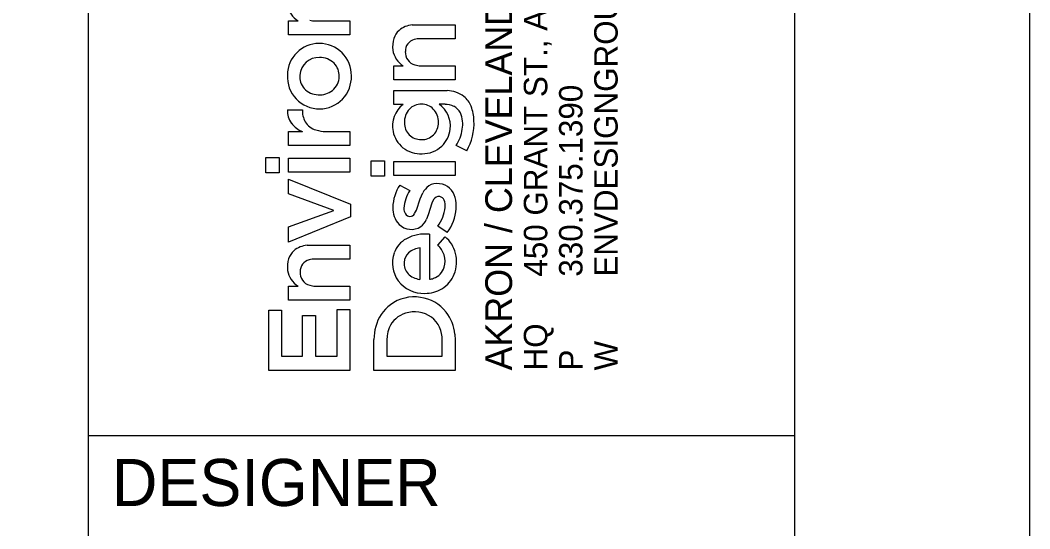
# Model space of a CAD drawing. Extents: x -0.3 to 34, y 0 to 22.
# Drawn here: x 31.855 to 34, y 2.302 to 3.382 of the extents above; entities that cross this region are included whole.
import ezdxf

# ---------------------------------------------------------------- set-up
doc = ezdxf.new("R2010")
doc.units = 0
for name, color, linetype in [('PM_X_CL_Pass_Proh_Lt', 7, 'Continuous'), ('PM_X_Edge_Line', 7, 'Continuous'), ('PM_X_Stop_Line', 7, 'Continuous')]:
    doc.layers.add(name, color=color, linetype=linetype)

msp = doc.modelspace()

# ---------------------------------------------------------------- linework, layer by layer
at = {"layer": 'PM_X_CL_Pass_Proh_Lt'}
msp.add_lwpolyline([(0, 0), (34, 0), (34, 22), (0, 22)], close=True, dxfattribs=at)
at = {"layer": 'PM_X_Edge_Line'}
for p, q in [((32.4254, 3.3509), (32.4254, 3.3807)), ((32.4254, 3.3807), (32.4455, 3.3807)), ((32.4822, 3.3807), (32.5557, 3.3807)), ((32.5557, 3.3807), (32.5557, 3.351)), ((32.6878, 3.3722), (32.6963, 3.3727)), ((32.6963, 3.3727), (32.7792, 3.3727)), ((32.7792, 3.3727), (32.7792, 3.3429)), ((32.5557, 3.351), (32.4254, 3.3509)), ((32.7792, 3.3429), (32.7048, 3.3428)), ((32.6489, 3.2557), (32.6489, 3.2855)), ((32.6489, 3.2855), (32.669, 3.2855)), ((32.7057, 3.2855), (32.7791, 3.2855)), ((32.7791, 3.2855), (32.7792, 3.2558)), ((32.7792, 3.2558), (32.6489, 3.2557)), ((32.6489, 3.2034), (32.6489, 3.2332)), ((32.6489, 3.2332), (32.7524, 3.2332)), ((32.7524, 3.2332), (32.7619, 3.2329)), ((32.6684, 3.2034), (32.6489, 3.2034)), ((32.7576, 3.2036), (32.7449, 3.2036)), ((32.423, 3.1919), (32.4545, 3.1919)), ((32.4254, 3.1159), (32.4254, 3.1458)), ((32.4254, 3.1458), (32.4547, 3.1458)), ((32.5041, 3.1458), (32.5557, 3.1457)), ((32.5557, 3.1457), (32.5556, 3.1159)), ((32.5556, 3.1159), (32.4254, 3.1159)), ((32.8036, 3.1049), (32.7812, 3.116)), ((32.3771, 3.0582), (32.3771, 3.0903)), ((32.3771, 3.0903), (32.4054, 3.0903)), ((32.4054, 3.0903), (32.4054, 3.0582)), ((32.4254, 3.0594), (32.4254, 3.0893)), ((32.4254, 3.0893), (32.5557, 3.0893)), ((32.5557, 3.0893), (32.5557, 3.0594)), ((32.6005, 3.0511), (32.6005, 3.0832)), ((32.6005, 3.0832), (32.6289, 3.0832)), ((32.6289, 3.0832), (32.6289, 3.0511)), ((32.6489, 3.0523), (32.6489, 3.0822)), ((32.6489, 3.0822), (32.7792, 3.0822)), ((32.7792, 3.0822), (32.7792, 3.0523)), ((32.4054, 3.0582), (32.3771, 3.0582)), ((32.5557, 3.0594), (32.4254, 3.0594)), ((32.6289, 3.0511), (32.6005, 3.0511)), ((32.7792, 3.0523), (32.6489, 3.0523)), ((32.4254, 3.0133), (32.4254, 3.0446)), ((32.4254, 3.0446), (32.5567, 2.9913)), ((32.6615, 3.0321), (32.6827, 3.0203)), ((32.5212, 2.978), (32.4254, 3.0133)), ((32.7048, 3.0026), (32.7104, 3.0153)), ((32.5567, 2.9913), (32.5567, 2.9644)), ((32.6967, 2.9787), (32.7048, 3.0026)), ((32.7298, 2.9933), (32.7221, 2.9688)), ((32.7334, 3.001), (32.7298, 2.9933)), ((32.4254, 2.9429), (32.5212, 2.978)), ((32.5567, 2.9644), (32.4254, 2.9109)), ((32.693, 2.9712), (32.6967, 2.9787)), ((32.7221, 2.9688), (32.7182, 2.9592)), ((32.4254, 2.9109), (32.4254, 2.9429)), ((32.7621, 2.9314), (32.742, 2.9447)), ((32.7245, 2.9275), (32.7246, 2.8319)), ((32.7423, 2.9046), (32.7577, 2.922)), ((32.4644, 2.904), (32.4729, 2.9044)), ((32.4729, 2.9044), (32.5557, 2.9044)), ((32.5557, 2.9044), (32.5557, 2.8746)), ((32.7049, 2.8318), (32.7049, 2.8983)), ((32.5557, 2.8746), (32.4814, 2.8746)), ((32.7036, 2.8317), (32.7049, 2.8318)), ((32.4254, 2.7875), (32.4254, 2.8173)), ((32.4254, 2.8173), (32.4455, 2.8173)), ((32.4822, 2.8173), (32.5557, 2.8173)), ((32.5557, 2.8173), (32.5557, 2.7876)), ((32.5557, 2.7876), (32.4254, 2.7875)), ((32.5286, 2.6683), (32.5286, 2.7672)), ((32.5286, 2.7672), (32.5557, 2.7672)), ((32.5557, 2.7672), (32.5557, 2.6379)), ((32.383, 2.6379), (32.383, 2.766)), ((32.383, 2.766), (32.4101, 2.766)), ((32.4101, 2.766), (32.4101, 2.6683)), ((32.455, 2.6683), (32.455, 2.7549)), ((32.455, 2.7549), (32.4822, 2.7549)), ((32.4822, 2.7549), (32.4822, 2.6683)), ((32.6064, 2.638), (32.6064, 2.704)), ((32.6347, 2.7118), (32.6341, 2.7023)), ((32.7785, 2.715), (32.7792, 2.7021)), ((32.6341, 2.7023), (32.6341, 2.6684)), ((32.7515, 2.6683), (32.7515, 2.7024)), ((32.7792, 2.7021), (32.7792, 2.638)), ((32.4101, 2.6683), (32.455, 2.6683)), ((32.4822, 2.6683), (32.5286, 2.6683)), ((32.6341, 2.6684), (32.7515, 2.6683)), ((32.5557, 2.6379), (32.383, 2.6379)), ((32.7792, 2.638), (32.6064, 2.638))]:
    msp.add_line(p, q, dxfattribs=at)
for points in [[(32.4254, 3.3509), (32.4254, 3.3807), (32.4455, 3.3807)], [(32.4822, 3.3807), (32.5557, 3.3807), (32.5557, 3.351), (32.4254, 3.3509)], [(32.6878, 3.3722), (32.6963, 3.3727), (32.7792, 3.3727), (32.7792, 3.3429), (32.7048, 3.3428)], [(32.6489, 3.2557), (32.6489, 3.2855), (32.669, 3.2855)], [(32.7057, 3.2855), (32.7791, 3.2855), (32.7792, 3.2558), (32.6489, 3.2557)], [(32.6684, 3.2034), (32.6489, 3.2034), (32.6489, 3.2332), (32.7524, 3.2332), (32.7619, 3.2329)], [(32.7576, 3.2036), (32.7449, 3.2036)], [(32.423, 3.1919), (32.4545, 3.1919)], [(32.4254, 3.1159), (32.4254, 3.1458), (32.4547, 3.1458)], [(32.5041, 3.1458), (32.5557, 3.1457), (32.5556, 3.1159), (32.4254, 3.1159)], [(32.8036, 3.1049), (32.7812, 3.116)], [(32.6615, 3.0321), (32.6827, 3.0203)], [(32.693, 2.9712), (32.6967, 2.9787), (32.7048, 3.0026), (32.7104, 3.0153)], [(32.7334, 3.001), (32.7298, 2.9933), (32.7221, 2.9688), (32.7182, 2.9592)], [(32.7621, 2.9314), (32.742, 2.9447)], [(32.7245, 2.9275), (32.7246, 2.8319)], [(32.7423, 2.9046), (32.7577, 2.922)], [(32.4644, 2.904), (32.4729, 2.9044), (32.5557, 2.9044), (32.5557, 2.8746), (32.4814, 2.8746)], [(32.7036, 2.8317), (32.7049, 2.8318), (32.7049, 2.8983)], [(32.4254, 2.7875), (32.4254, 2.8173), (32.4455, 2.8173)], [(32.4822, 2.8173), (32.5557, 2.8173), (32.5557, 2.7876), (32.4254, 2.7875)], [(32.7785, 2.715), (32.7792, 2.7021), (32.7792, 2.638), (32.6064, 2.638)], [(32.6064, 2.638), (32.6064, 2.704)], [(32.6347, 2.7118), (32.6341, 2.7023), (32.6341, 2.6684), (32.7515, 2.6683), (32.7515, 2.7024)]]:
    msp.add_lwpolyline(points, dxfattribs=at)
for points in [[(32.3771, 3.0582), (32.3771, 3.0903), (32.4054, 3.0903), (32.4054, 3.0582)], [(32.4254, 3.0594), (32.4254, 3.0893), (32.5557, 3.0893), (32.5557, 3.0594)], [(32.6005, 3.0511), (32.6005, 3.0832), (32.6289, 3.0832), (32.6289, 3.0511)], [(32.6489, 3.0523), (32.6489, 3.0822), (32.7792, 3.0822), (32.7792, 3.0523)], [(32.4254, 2.9109), (32.4254, 2.9429), (32.5212, 2.978), (32.4254, 3.0133), (32.4254, 3.0446), (32.5567, 2.9913), (32.5567, 2.9644)], [(32.383, 2.6379), (32.383, 2.766), (32.4101, 2.766), (32.4101, 2.6683), (32.455, 2.6683), (32.455, 2.7549), (32.4822, 2.7549), (32.4822, 2.6683), (32.5286, 2.6683), (32.5286, 2.7672), (32.5557, 2.7672), (32.5557, 2.6379)]]:
    msp.add_lwpolyline(points, close=True, dxfattribs=at)
for centre, radius, start, end in [((32.4703, 3.4214), 0.0476, 188.9646, 238.6987), ((32.4703, 3.4214), 0.0476, 188.9646, 238.6987), ((32.4818, 3.4229), 0.0421, 254.0891, 270.5284), ((32.4818, 3.4229), 0.0421, 254.0891, 270.5284), ((32.6922, 3.3225), 0.0499, 94.9706, 130.2248), ((32.6922, 3.3225), 0.0499, 94.9706, 130.2248), ((32.6869, 3.3309), 0.0402, 132.2238, 161.6823), ((32.6869, 3.3309), 0.0402, 132.2238, 161.6823), ((32.4901, 3.2654), 0.0674, 89.8476, 179.6405), ((32.4901, 3.2654), 0.0674, 89.8476, 179.6405), ((32.4906, 3.2647), 0.0681, 359.5401, 90.2114), ((32.4906, 3.2647), 0.0681, 359.5401, 90.2114), ((32.7022, 3.3264), 0.056, 162.274, 187.7917), ((32.7022, 3.3264), 0.056, 162.274, 187.7917), ((32.6983, 3.3169), 0.025, 103.6868, 182.214), ((32.6983, 3.3169), 0.025, 103.6868, 182.214), ((32.7045, 3.2968), 0.046, 89.6051, 105.3303), ((32.7045, 3.2968), 0.046, 89.6051, 105.3303), ((32.6937, 3.3262), 0.0476, 188.9646, 238.6987), ((32.6937, 3.3262), 0.0476, 188.9646, 238.6987), ((32.7008, 3.3138), 0.0276, 175.5844, 255.1382), ((32.7008, 3.3138), 0.0276, 175.5844, 255.1382), ((32.4892, 3.2626), 0.0404, 87.0481, 175.5726), ((32.4892, 3.2626), 0.0404, 87.0481, 175.5726), ((32.492, 3.26), 0.043, 45.8426, 90.9801), ((32.492, 3.26), 0.043, 45.8426, 90.9801), ((32.4946, 3.2642), 0.0382, 357.8857, 44.159), ((32.4946, 3.2642), 0.0382, 357.8857, 44.159), ((32.7053, 3.3277), 0.0421, 254.0891, 270.5284), ((32.7053, 3.3277), 0.0421, 254.0891, 270.5284), ((32.4908, 3.2621), 0.0682, 176.8344, 270.4038), ((32.4908, 3.2621), 0.0682, 176.8344, 270.4038), ((32.4873, 3.2625), 0.0385, 175.1538, 221.1471), ((32.4873, 3.2625), 0.0385, 175.1538, 221.1471), ((32.4912, 3.2614), 0.0675, 270.0624, 2.3776), ((32.4912, 3.2614), 0.0675, 270.0624, 2.3776), ((32.4945, 3.2632), 0.0383, 308.2894, 359.4347), ((32.4945, 3.2632), 0.0383, 308.2894, 359.4347), ((32.4892, 3.2661), 0.0423, 223.0999, 268.8089), ((32.4892, 3.2661), 0.0423, 223.0999, 268.8089), ((32.491, 3.2679), 0.0442, 266.5651, 308.0608), ((32.491, 3.2679), 0.0442, 266.5651, 308.0608), ((32.7591, 3.1679), 0.065, 53.4034, 87.4906), ((32.7591, 3.1679), 0.065, 53.4034, 87.4906), ((32.7652, 3.1804), 0.0514, 21.6075, 50.5577), ((32.7652, 3.1804), 0.0514, 21.6075, 50.5577), ((32.7029, 3.1581), 0.0569, 127.3748, 192.2247), ((32.7029, 3.1581), 0.0569, 127.3748, 192.2247), ((32.7069, 3.1693), 0.0346, 88.473, 136.4256), ((32.7069, 3.1693), 0.0346, 88.473, 136.4256), ((32.7081, 3.1696), 0.0342, 44.2719, 90.4762), ((32.7081, 3.1696), 0.0342, 44.2719, 90.4762), ((32.7142, 3.1583), 0.0547, 352.1125, 55.923), ((32.7142, 3.1583), 0.0547, 352.1125, 55.923), ((32.7567, 3.1572), 0.0463, 65.0169, 88.8011), ((32.7567, 3.1572), 0.0463, 65.0169, 88.8011), ((32.7626, 3.1716), 0.0309, 26.2681, 63.803), ((32.7626, 3.1716), 0.0309, 26.2681, 63.803), ((32.7307, 3.1671), 0.0884, 1.1514, 21.3627), ((32.7307, 3.1671), 0.0884, 1.1514, 21.3627), ((32.4662, 3.1888), 0.0433, 175.8731, 216.3475), ((32.4662, 3.1888), 0.0433, 175.8731, 216.3475), ((32.5009, 3.1895), 0.0464, 176.9688, 209.6064), ((32.5009, 3.1895), 0.0464, 176.9688, 209.6064), ((32.7114, 3.166), 0.0401, 137.4674, 182.3324), ((32.7114, 3.166), 0.0401, 137.4674, 182.3324), ((32.7037, 3.166), 0.04, 358.5714, 43.5376), ((32.7037, 3.166), 0.04, 358.5714, 43.5376), ((32.7357, 3.1615), 0.0595, 349.3073, 23.4307), ((32.7357, 3.1615), 0.0595, 349.3073, 23.4307), ((32.4747, 3.1972), 0.0551, 218.0981, 248.7907), ((32.4747, 3.1972), 0.0551, 218.0981, 248.7907), ((32.4951, 3.1881), 0.0408, 211.9447, 253.2028), ((32.4951, 3.1881), 0.0408, 211.9447, 253.2028), ((32.7065, 3.1637), 0.0351, 178.8821, 271.0837), ((32.7065, 3.1637), 0.0351, 178.8821, 271.0837), ((32.7082, 3.164), 0.0355, 268.2788, 1.5502), ((32.7082, 3.164), 0.0355, 268.2788, 1.5502), ((32.7054, 3.1624), 0.1138, 329.6388, 3.26), ((32.7054, 3.1624), 0.1138, 329.6388, 3.26), ((32.5047, 3.2165), 0.0707, 252.4655, 269.573), ((32.5047, 3.2165), 0.0707, 252.4655, 269.573), ((32.7046, 3.157), 0.0584, 190.7518, 231.2892), ((32.7046, 3.157), 0.0584, 190.7518, 231.2892), ((32.7099, 3.1571), 0.0589, 313.742, 353.8554), ((32.7099, 3.1571), 0.0589, 313.742, 353.8554), ((32.7074, 3.1633), 0.0877, 327.3149, 351.5748), ((32.7074, 3.1633), 0.0877, 327.3149, 351.5748), ((32.7063, 3.1611), 0.0627, 232.4606, 272.5902), ((32.7063, 3.1611), 0.0627, 232.4606, 272.5902), ((32.7095, 3.159), 0.0605, 269.6361, 312.7088), ((32.7095, 3.159), 0.0605, 269.6361, 312.7088), ((32.7364, 2.9826), 0.0897, 146.531, 178.7571), ((32.7364, 2.9826), 0.0897, 146.531, 178.7571), ((32.7466, 2.9971), 0.0405, 125.5118, 153.4159), ((32.7466, 2.9971), 0.0405, 125.5118, 153.4159), ((32.7406, 3.0026), 0.0326, 80.1719, 122.5197), ((32.7406, 3.0026), 0.0326, 80.1719, 122.5197), ((32.7428, 2.9982), 0.0367, 47.7934, 84.6892), ((32.7428, 2.9982), 0.0367, 47.7934, 84.6892), ((32.7379, 2.9946), 0.0427, 14.9966, 46.2063), ((32.7379, 2.9946), 0.0427, 14.9966, 46.2063), ((32.7452, 2.9789), 0.0749, 146.5112, 176.9101), ((32.7452, 2.9789), 0.0749, 146.5112, 176.9101), ((32.7438, 2.9963), 0.0114, 76.6609, 155.7053), ((32.7438, 2.9963), 0.0114, 76.6609, 155.7053), ((32.744, 2.9951), 0.0126, 21.5098, 78.5262), ((32.744, 2.9951), 0.0126, 21.5098, 78.5262), ((32.7104, 2.9867), 0.0712, 355.8306, 15.3914), ((32.7104, 2.9867), 0.0712, 355.8306, 15.3914), ((32.6967, 2.9824), 0.0501, 177.5366, 222.7932), ((32.6967, 2.9824), 0.0501, 177.5366, 222.7932), ((32.6931, 2.9823), 0.0228, 178.4747, 211.0868), ((32.6931, 2.9823), 0.0228, 178.4747, 211.0868), ((32.6825, 2.9915), 0.0757, 321.811, 354.7969), ((32.6825, 2.9915), 0.0757, 321.811, 354.7969), ((32.7259, 2.9877), 0.0321, 354.5726, 22.068), ((32.7259, 2.9877), 0.0321, 354.5726, 22.068), ((32.6895, 2.9882), 0.0922, 321.9777, 355.8738), ((32.6895, 2.9882), 0.0922, 321.9777, 355.8738), ((32.6833, 2.9767), 0.0115, 212.2368, 268.3777), ((32.6833, 2.9767), 0.0115, 212.2368, 268.3777), ((32.6834, 2.9759), 0.0107, 267.716, 333.7337), ((32.6834, 2.9759), 0.0107, 267.716, 333.7337), ((32.686, 2.9753), 0.0375, 225.9854, 302.4797), ((32.686, 2.9753), 0.0375, 225.9854, 302.4797), ((32.681, 2.9758), 0.0408, 308.0877, 335.9874), ((32.681, 2.9758), 0.0408, 308.0877, 335.9874), ((32.7024, 2.8691), 0.0558, 118.8308, 160.6244), ((32.7024, 2.8691), 0.0558, 118.8308, 160.6244), ((32.7152, 2.8441), 0.0838, 83.615, 118.2876), ((32.7152, 2.8441), 0.0838, 83.615, 118.2876), ((32.7174, 2.8717), 0.0644, 13.5336, 51.3615), ((32.7174, 2.8717), 0.0644, 13.5336, 51.3615), ((32.4687, 2.8543), 0.0499, 94.9696, 130.2225), ((32.4687, 2.8543), 0.0499, 94.9696, 130.2225), ((32.7079, 2.8561), 0.0424, 94.008, 130.8817), ((32.7079, 2.8561), 0.0424, 94.008, 130.8817), ((32.7038, 2.8656), 0.0549, 19.0357, 45.4406), ((32.7038, 2.8656), 0.0549, 19.0357, 45.4406), ((32.4787, 2.8582), 0.056, 162.2736, 187.7919), ((32.4787, 2.8582), 0.056, 162.2736, 187.7919), ((32.4635, 2.8626), 0.0402, 132.2219, 161.6818), ((32.4635, 2.8626), 0.0402, 132.2219, 161.6818), ((32.4811, 2.8286), 0.046, 89.6049, 105.3284), ((32.4811, 2.8286), 0.046, 89.6049, 105.3284), ((32.7104, 2.8661), 0.0644, 160.5201, 215.7831), ((32.7104, 2.8661), 0.0644, 160.5201, 215.7831), ((32.7005, 2.8663), 0.0298, 132.9851, 177.179), ((32.7005, 2.8663), 0.0298, 132.9851, 177.179), ((32.7107, 2.8697), 0.047, 344.6059, 17.007), ((32.7107, 2.8697), 0.047, 344.6059, 17.007), ((32.7064, 2.8692), 0.0758, 339.3542, 13.3785), ((32.7064, 2.8692), 0.0758, 339.3542, 13.3785), ((32.4748, 2.8487), 0.025, 103.6865, 182.2187), ((32.4748, 2.8487), 0.025, 103.6865, 182.2187), ((32.7017, 2.865), 0.0311, 175.0013, 223.283), ((32.7017, 2.865), 0.0311, 175.0013, 223.283), ((32.7224, 2.8671), 0.035, 288.0077, 343.5508), ((32.7224, 2.8671), 0.035, 288.0077, 343.5508), ((32.4703, 2.858), 0.0476, 188.962, 238.7037), ((32.4703, 2.858), 0.0476, 188.962, 238.7037), ((32.4773, 2.8456), 0.0276, 175.5854, 255.1439), ((32.4773, 2.8456), 0.0276, 175.5854, 255.1439), ((32.7089, 2.8736), 0.0423, 225.0619, 262.7974), ((32.7089, 2.8736), 0.0423, 225.0619, 262.7974), ((32.7247, 2.8522), 0.0202, 269.7003, 294.8711), ((32.7247, 2.8522), 0.0202, 269.7003, 294.8711), ((32.7189, 2.8652), 0.0626, 300.9427, 338.7323), ((32.7189, 2.8652), 0.0626, 300.9427, 338.7323), ((32.4818, 2.8595), 0.0422, 254.0916, 270.5284), ((32.4818, 2.8595), 0.0422, 254.0916, 270.5284), ((32.7125, 2.8705), 0.0687, 217.7452, 271.6543), ((32.7125, 2.8705), 0.0687, 217.7452, 271.6543), ((32.7155, 2.8724), 0.0706, 269.2048, 300.3341), ((32.7155, 2.8724), 0.0706, 269.2048, 300.3341), ((32.6923, 2.7079), 0.0864, 81.194, 125.9984), ((32.6923, 2.7079), 0.0864, 81.194, 125.9984), ((32.6946, 2.7113), 0.0827, 37.8521, 82.402), ((32.6946, 2.7113), 0.0827, 37.8521, 82.402), ((32.6939, 2.7089), 0.0865, 127.2362, 165.148), ((32.6939, 2.7089), 0.0865, 127.2362, 165.148), ((32.6889, 2.7078), 0.054, 106.1881, 157.3861), ((32.6889, 2.7078), 0.054, 106.1881, 157.3861), ((32.6928, 2.6986), 0.0639, 55.6727, 107.2093), ((32.6928, 2.6986), 0.0639, 55.6727, 107.2093), ((32.6929, 2.705), 0.0587, 357.4662, 52.2665), ((32.6929, 2.705), 0.0587, 357.4662, 52.2665), ((32.6859, 2.7057), 0.0931, 5.7333, 37.304), ((32.6859, 2.7057), 0.0931, 5.7333, 37.304), ((32.7143, 2.7028), 0.1078, 164.7861, 179.3704), ((32.7143, 2.7028), 0.1078, 164.7861, 179.3704), ((32.6983, 2.7039), 0.0641, 157.3571, 172.9275), ((32.6983, 2.7039), 0.0641, 157.3571, 172.9275)]:
    msp.add_arc(centre, radius, start, end, dxfattribs=at)
at = {"layer": 'PM_X_Stop_Line'}
for p, q in [((32, 0.5), (32, 21.5)), ((32, 2.5), (33.5, 2.5))]:
    msp.add_line(p, q, dxfattribs=at)
msp.add_lwpolyline([(1.5, 21.5), (33.5, 21.5), (33.5, 0.5), (1.5, 0.5)], close=True, dxfattribs=at)

# ---------------------------------------------------------------- texts
at = {"layer": 'PM_X_Edge_Line'}
for s, height, p in [('450 GRANT ST., AKRON, OH  44311', 0.049846, (32.9749, 2.8374)), ('AKRON / CLEVELAND / COLUMBUS', 0.056969, (32.9001, 2.638)), ('ENVDESIGNGROUP.COM', 0.049846, (33.1244, 2.8374)), ('330.375.1390', 0.049846, (33.0497, 2.8374)), ('HQ ', 0.04985, (32.9749, 2.638)), ('W', 0.0498, (33.1244, 2.638)), ('P', 0.0498, (33.0497, 2.638))]:
    msp.add_text(s, height=height, rotation=90, dxfattribs=at).set_placement(p)
msp.add_text('DESIGNER', height=0.1, dxfattribs=at).set_placement((32.05, 2.35))

doc.saveas('drawing.dxf')
